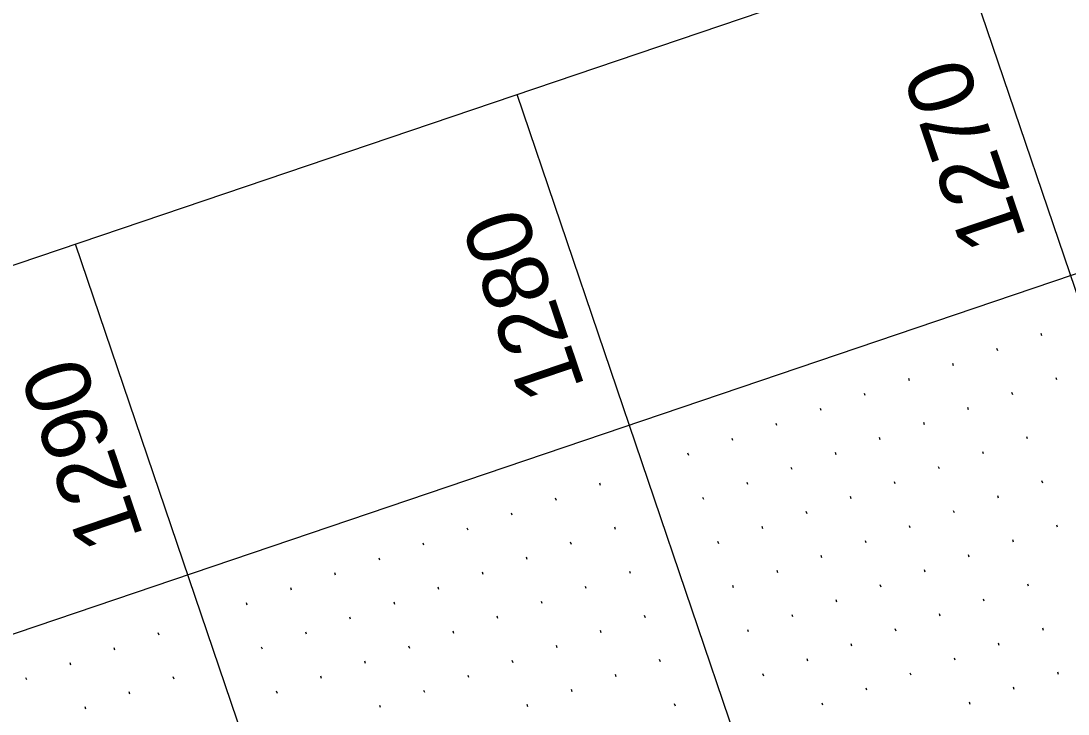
# Model space of a CAD drawing. Extents: x 2150318 to 2152065, y 143281 to 145371.
# Drawn here: x 2151178.4 to 2151290.7, y 145180.3 to 145254.7 of the extents above; entities that cross this region are included whole.
import ezdxf

# ---------------------------------------------------------------- set-up
doc = ezdxf.new("R2010")
doc.units = 0
for name, color, linetype in [('SHT_Plan_Profile_Sheet_Elev_Txt', 7, 'Continuous'), ('SHT_Profile_Grid_Major', 7, 'Continuous'), ('SHT_Profile_Grid_Minor', 7, 'Continuous'), ('SHT_Sheet_Border', 7, 'Continuous')]:
    doc.layers.add(name, color=color, linetype=linetype)

msp = doc.modelspace()

# ---------------------------------------------------------------- linework, layer by layer
at = {"layer": 'SHT_Profile_Grid_Major'}
for p, q in [((2151784.91, 143771.34), (2151278.93, 145262.85)), ((2151737.57, 143755.28), (2151231.58, 145246.79)), ((2151690.22, 143739.22), (2151184.23, 145230.73))]:
    msp.add_line(p, q, dxfattribs=at)
at = {"layer": 'SHT_Profile_Grid_Minor'}
for p, q in [((2151287.88, 145220.88), (2151287.8, 145221.12)), ((2151283.15, 145219.28), (2151283.07, 145219.51)), ((2151278.41, 145217.67), (2151278.33, 145217.91)), ((2151273.68, 145216.06), (2151273.6, 145216.3)), ((2151289.49, 145216.15), (2151289.41, 145216.38)), ((2151268.94, 145214.46), (2151268.86, 145214.69)), ((2151284.76, 145214.54), (2151284.67, 145214.78)), ((2151264.21, 145212.85), (2151264.13, 145213.09)), ((2151280.02, 145212.93), (2151279.94, 145213.17)), ((2151259.47, 145211.24), (2151259.39, 145211.48)), ((2151275.29, 145211.33), (2151275.21, 145211.56)), ((2151270.55, 145209.72), (2151270.47, 145209.96)), ((2151286.36, 145209.81), (2151286.28, 145210.04)), ((2151254.74, 145209.64), (2151254.66, 145209.87)), ((2151250, 145208.03), (2151249.92, 145208.27)), ((2151265.82, 145208.11), (2151265.74, 145208.35)), ((2151281.63, 145208.2), (2151281.55, 145208.44)), ((2151261.08, 145206.51), (2151261, 145206.75)), ((2151276.89, 145206.59), (2151276.81, 145206.83)), ((2151240.53, 145204.82), (2151240.45, 145205.05)), ((2151256.35, 145204.9), (2151256.27, 145205.14)), ((2151272.16, 145204.99), (2151272.08, 145205.22)), ((2151287.97, 145205.07), (2151287.89, 145205.31)), ((2151235.8, 145203.21), (2151235.72, 145203.45)), ((2151251.61, 145203.3), (2151251.53, 145203.53)), ((2151267.42, 145203.38), (2151267.34, 145203.62)), ((2151283.23, 145203.46), (2151283.15, 145203.7)), ((2151278.5, 145201.86), (2151278.42, 145202.09)), ((2151231.06, 145201.61), (2151230.98, 145201.84)), ((2151262.69, 145201.77), (2151262.61, 145202.01)), ((2151226.33, 145200), (2151226.25, 145200.24)), ((2151242.14, 145200.08), (2151242.06, 145200.32)), ((2151257.95, 145200.17), (2151257.87, 145200.4)), ((2151273.76, 145200.25), (2151273.68, 145200.49)), ((2151289.57, 145200.34), (2151289.49, 145200.57)), ((2151237.41, 145198.48), (2151237.33, 145198.71)), ((2151253.22, 145198.56), (2151253.14, 145198.8)), ((2151269.03, 145198.64), (2151268.95, 145198.88)), ((2151284.84, 145198.73), (2151284.76, 145198.97)), ((2151221.59, 145198.39), (2151221.51, 145198.63)), ((2151216.86, 145196.79), (2151216.78, 145197.02)), ((2151232.67, 145196.87), (2151232.59, 145197.11)), ((2151264.29, 145197.04), (2151264.21, 145197.28)), ((2151280.1, 145197.12), (2151280.02, 145197.36)), ((2151212.12, 145195.18), (2151212.04, 145195.42)), ((2151227.94, 145195.26), (2151227.86, 145195.5)), ((2151243.75, 145195.35), (2151243.67, 145195.59)), ((2151259.56, 145195.43), (2151259.48, 145195.67)), ((2151275.37, 145195.52), (2151275.29, 145195.75)), ((2151286.45, 145193.99), (2151286.37, 145194.23)), ((2151207.39, 145193.57), (2151207.31, 145193.81)), ((2151223.2, 145193.66), (2151223.12, 145193.89)), ((2151239.01, 145193.74), (2151238.93, 145193.98)), ((2151254.82, 145193.83), (2151254.74, 145194.06)), ((2151270.63, 145193.91), (2151270.55, 145194.15)), ((2151202.65, 145191.97), (2151202.57, 145192.2)), ((2151218.47, 145192.05), (2151218.39, 145192.29)), ((2151234.28, 145192.14), (2151234.2, 145192.37)), ((2151265.9, 145192.3), (2151265.82, 145192.54)), ((2151281.71, 145192.39), (2151281.63, 145192.62)), ((2151245.35, 145190.61), (2151245.27, 145190.85)), ((2151261.16, 145190.7), (2151261.08, 145190.93)), ((2151276.98, 145190.78), (2151276.9, 145191.02)), ((2151213.73, 145190.45), (2151213.65, 145190.68)), ((2151229.54, 145190.53), (2151229.46, 145190.77)), ((2151193.18, 145188.76), (2151193.1, 145188.99)), ((2151209, 145188.84), (2151208.92, 145189.08)), ((2151224.81, 145188.92), (2151224.73, 145189.16)), ((2151240.62, 145189.01), (2151240.54, 145189.24)), ((2151256.43, 145189.09), (2151256.35, 145189.33)), ((2151272.24, 145189.18), (2151272.16, 145189.41)), ((2151288.05, 145189.26), (2151287.97, 145189.5)), ((2151204.26, 145187.23), (2151204.18, 145187.47)), ((2151220.07, 145187.32), (2151219.99, 145187.55)), ((2151235.88, 145187.4), (2151235.8, 145187.64)), ((2151267.51, 145187.57), (2151267.43, 145187.81)), ((2151283.32, 145187.65), (2151283.24, 145187.89)), ((2151188.45, 145187.15), (2151188.37, 145187.39)), ((2151183.72, 145185.54), (2151183.63, 145185.78)), ((2151215.34, 145185.71), (2151215.26, 145185.95)), ((2151231.15, 145185.79), (2151231.07, 145186.03)), ((2151246.96, 145185.88), (2151246.88, 145186.12)), ((2151262.77, 145185.96), (2151262.69, 145186.2)), ((2151278.58, 145186.05), (2151278.5, 145186.28)), ((2151178.98, 145183.94), (2151178.9, 145184.17)), ((2151194.79, 145184.02), (2151194.71, 145184.26)), ((2151210.6, 145184.1), (2151210.52, 145184.34)), ((2151226.41, 145184.19), (2151226.33, 145184.42)), ((2151242.22, 145184.27), (2151242.14, 145184.51)), ((2151258.04, 145184.36), (2151257.96, 145184.59)), ((2151273.85, 145184.44), (2151273.77, 145184.68)), ((2151289.66, 145184.52), (2151289.58, 145184.76)), ((2151269.11, 145182.83), (2151269.03, 145183.07)), ((2151284.92, 145182.92), (2151284.84, 145183.15)), ((2151190.06, 145182.41), (2151189.98, 145182.65)), ((2151205.87, 145182.5), (2151205.79, 145182.73)), ((2151221.68, 145182.58), (2151221.6, 145182.82)), ((2151237.49, 145182.67), (2151237.41, 145182.9)), ((2151185.32, 145180.81), (2151185.24, 145181.04)), ((2151216.94, 145180.98), (2151216.86, 145181.21)), ((2151232.75, 145181.06), (2151232.67, 145181.3)), ((2151248.57, 145181.14), (2151248.49, 145181.38)), ((2151264.38, 145181.23), (2151264.3, 145181.46)), ((2151280.19, 145181.31), (2151280.11, 145181.55))]:
    msp.add_line(p, q, dxfattribs=at)
at = {"layer": 'SHT_Sheet_Border'}
msp.add_line((2151362, 145251.44), (2150912.18, 145098.84), dxfattribs=at)
msp.add_lwpolyline([(2150901.85, 143471.77), (2150395.86, 144963.28), (2151390.2, 145300.6), (2151896.19, 143809.09)], close=True, dxfattribs=at)

# ---------------------------------------------------------------- texts
at = {"layer": 'SHT_Plan_Profile_Sheet_Elev_Txt'}
for s, p in [('1270', (2151286.25, 145231.44)), ('1280', (2151238.9, 145215.37)), ('1290', (2151191.55, 145199.31))]:
    msp.add_text(s, height=7, rotation=108.7393, dxfattribs=at).set_placement(p)

doc.saveas('drawing.dxf')
